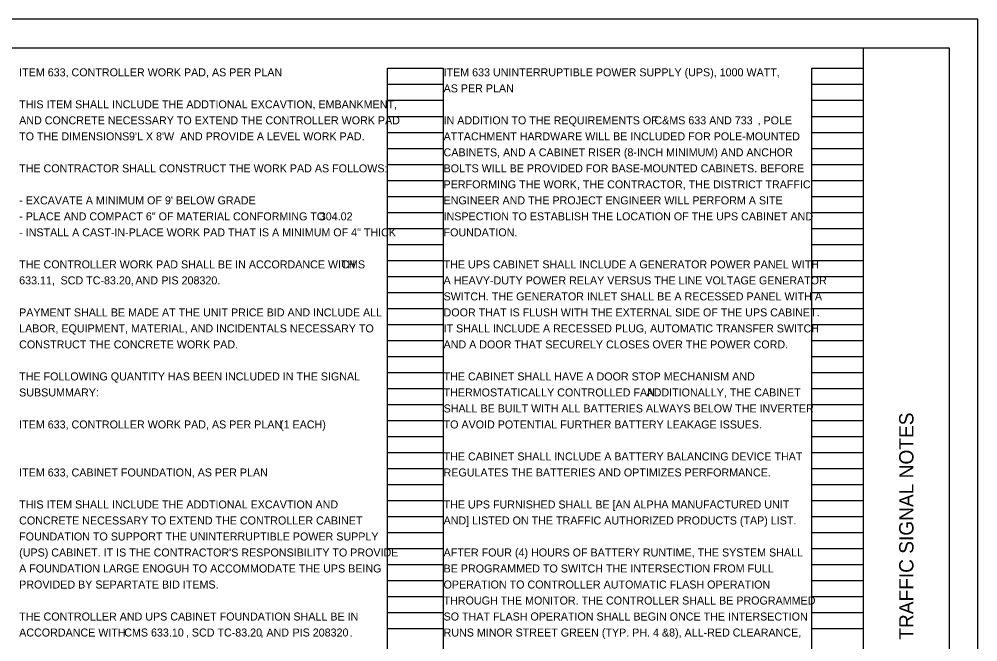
# Model space of a CAD drawing. Extents: x 0 to 34, y 0 to 22.
# Drawn here: x 17.24 to 34, y 11.11 to 22 of the extents above; entities that cross this region are included whole.
import ezdxf

# ---------------------------------------------------------------- set-up
doc = ezdxf.new("R2010")
doc.units = 0
for name, color, linetype in [('SH_Border', 7, 'Continuous'), ('SH_Cut_Line', 7, 'Continuous'), ('SH_Data', 7, 'Continuous'), ('SH_Text', 7, 'Continuous')]:
    doc.layers.add(name, color=color, linetype=linetype)

msp = doc.modelspace()

# ---------------------------------------------------------------- linework, layer by layer
at = {"layer": 'SH_Border'}
msp.add_line((32, 0.5), (32, 21.5), dxfattribs=at)
msp.add_lwpolyline([(1.5, 21.5), (33.5, 21.5), (33.5, 0.5), (1.5, 0.5)], close=True, dxfattribs=at)
at = {"layer": 'SH_Cut_Line'}
msp.add_lwpolyline([(0, 0), (34, 0), (34, 22), (0, 22)], close=True, dxfattribs=at)
at = {"layer": 'SH_Data'}
for p, q in [((23.68, 0.98), (23.68, 21.14)), ((23.68, 21.14), (24.66, 21.14)), ((24.66, 0.98), (24.66, 21.14)), ((31.1, 0.98), (31.1, 21.14)), ((31.1, 21.14), (32, 21.14)), ((32, 0.98), (32, 21.14)), ((23.68, 20.86), (24.66, 20.86)), ((31.1, 20.86), (32, 20.86)), ((23.68, 20.58), (24.66, 20.58)), ((31.1, 20.58), (32, 20.58)), ((23.68, 20.3), (24.66, 20.3)), ((31.1, 20.3), (32, 20.3)), ((23.68, 20.02), (24.66, 20.02)), ((31.1, 20.02), (32, 20.02)), ((23.68, 19.74), (24.66, 19.74)), ((31.1, 19.74), (32, 19.74)), ((23.68, 19.46), (24.66, 19.46)), ((31.1, 19.46), (32, 19.46)), ((23.68, 19.18), (24.66, 19.18)), ((31.1, 19.18), (32, 19.18)), ((23.68, 18.9), (24.66, 18.9)), ((31.1, 18.9), (32, 18.9)), ((23.68, 18.62), (24.66, 18.62)), ((31.1, 18.62), (32, 18.62)), ((23.68, 18.34), (24.66, 18.34)), ((31.1, 18.34), (32, 18.34)), ((23.68, 18.06), (24.66, 18.06)), ((31.1, 18.06), (32, 18.06)), ((23.68, 17.78), (24.66, 17.78)), ((31.1, 17.78), (32, 17.78)), ((23.68, 17.5), (24.66, 17.5)), ((31.1, 17.5), (32, 17.5)), ((23.68, 17.22), (24.66, 17.22)), ((31.1, 17.22), (32, 17.22)), ((23.68, 16.94), (24.66, 16.94)), ((31.1, 16.94), (32, 16.94)), ((23.68, 16.66), (24.66, 16.66)), ((31.1, 16.66), (32, 16.66)), ((23.68, 16.38), (24.66, 16.38)), ((31.1, 16.38), (32, 16.38)), ((23.68, 16.1), (24.66, 16.1)), ((31.1, 16.1), (32, 16.1)), ((23.68, 15.82), (24.66, 15.82)), ((31.1, 15.82), (32, 15.82)), ((23.68, 15.54), (24.66, 15.54)), ((31.1, 15.54), (32, 15.54)), ((23.68, 15.26), (24.66, 15.26)), ((31.1, 15.26), (32, 15.26)), ((23.68, 14.98), (24.66, 14.98)), ((31.1, 14.98), (32, 14.98)), ((23.68, 14.7), (24.66, 14.7)), ((31.1, 14.7), (32, 14.7)), ((23.68, 14.42), (24.66, 14.42)), ((31.1, 14.42), (32, 14.42)), ((23.68, 14.14), (24.66, 14.14)), ((31.1, 14.14), (32, 14.14)), ((23.68, 13.86), (24.66, 13.86)), ((31.1, 13.86), (32, 13.86)), ((23.68, 13.58), (24.66, 13.58)), ((31.1, 13.58), (32, 13.58)), ((23.68, 13.3), (24.66, 13.3)), ((31.1, 13.3), (32, 13.3)), ((23.68, 13.02), (24.66, 13.02)), ((31.1, 13.02), (32, 13.02)), ((23.68, 12.74), (24.66, 12.74)), ((31.1, 12.74), (32, 12.74)), ((23.68, 12.46), (24.66, 12.46)), ((31.1, 12.46), (32, 12.46)), ((23.68, 12.18), (24.66, 12.18)), ((31.1, 12.18), (32, 12.18)), ((23.68, 11.9), (24.66, 11.9)), ((31.1, 11.9), (32, 11.9)), ((23.68, 11.62), (24.66, 11.62)), ((31.1, 11.62), (32, 11.62)), ((23.68, 11.34), (24.66, 11.34)), ((31.1, 11.34), (32, 11.34))]:
    msp.add_line(p, q, dxfattribs=at)

# ---------------------------------------------------------------- texts
msp.add_text('TRAFFIC SIGNAL NOTES', height=0.25, rotation=90, dxfattribs=at).set_placement((32.875, 11.144))
at = {"layer": 'SH_Text'}
for s, p in [('ITEM 633, CONTROLLER WORK PAD, AS PER PLAN', (17.24, 21)), ('ITEM 633 UNINTERRUPTIBLE POWER SUPPLY (UPS), 1000 WATT,', (24.66, 21)), ('AS PER PLAN', (24.66, 20.72)), ('THIS ITEM SHALL INCLUDE THE ADDTIONAL EXCAVTION, EMBANKMENT,', (17.24, 20.44)), ('AND CONCRETE NECESSARY TO EXTEND THE CONTROLLER WORK PAD', (17.24, 20.16)), ('IN ADDITION TO THE REQUIREMENTS OF ', (24.66, 20.16)), ('C&MS 633 AND 733', (28.346, 20.16)), (', POLE', (30.149, 20.16)), ('TO THE DIMENSIONS ', (17.24, 19.88)), ("9'L X 8'W", (19.16, 19.88)), (' AND PROVIDE A LEVEL WORK PAD.', (20.001, 19.88)), ('ATTACHMENT HARDWARE WILL BE INCLUDED FOR POLE-MOUNTED', (24.66, 19.88)), ('CABINETS, AND A CABINET RISER (8-INCH MINIMUM) AND ANCHOR', (24.66, 19.6)), ('THE CONTRACTOR SHALL CONSTRUCT THE WORK PAD AS FOLLOWS:', (17.24, 19.32)), ('BOLTS WILL BE PROVIDED FOR BASE-MOUNTED CABINETS. BEFORE', (24.66, 19.32)), ('PERFORMING THE WORK, THE CONTRACTOR, THE DISTRICT TRAFFIC', (24.66, 19.04)), ("- EXCAVATE A MINIMUM OF 9' BELOW GRADE", (17.24, 18.76)), ('ENGINEER AND THE PROJECT ENGINEER WILL PERFORM A SITE', (24.66, 18.76)), ('- PLACE AND COMPACT 6" OF MATERIAL CONFORMING TO ', (17.24, 18.48)), ('304.02', (22.496, 18.48)), ('INSPECTION TO ESTABLISH THE LOCATION OF THE UPS CABINET AND', (24.66, 18.48)), ('- INSTALL A CAST-IN-PLACE WORK PAD THAT IS A MINIMUM OF 4" THICK', (17.24, 18.2)), ('FOUNDATION.', (24.66, 18.2)), ('THE CONTROLLER WORK PAD SHALL BE IN ACCORDANCE WITH ', (17.24, 17.64)), ('CMS', (22.872, 17.64)), ('THE UPS CABINET SHALL INCLUDE A GENERATOR POWER PANEL WITH', (24.66, 17.64)), ('633.11,', (17.24, 17.36)), ('SCD TC-83.20,', (17.964, 17.36)), (' AND ', (19.221, 17.36)), ('PIS 208320.', (19.726, 17.36)), ('A HEAVY-DUTY POWER RELAY VERSUS THE LINE VOLTAGE GENERATOR', (24.66, 17.36)), ('SWITCH. THE GENERATOR INLET SHALL BE A RECESSED PANEL WITH A', (24.66, 17.08)), ('PAYMENT SHALL BE MADE AT THE UNIT PRICE BID AND INCLUDE ALL', (17.24, 16.8)), ('DOOR THAT IS FLUSH WITH THE EXTERNAL SIDE OF THE UPS CABINET.', (24.66, 16.8)), ('LABOR, EQUIPMENT, MATERIAL, AND INCIDENTALS NECESSARY TO', (17.24, 16.52)), ('IT SHALL INCLUDE A RECESSED PLUG, AUTOMATIC TRANSFER SWITCH', (24.66, 16.52)), ('CONSTRUCT THE CONCRETE WORK PAD.', (17.24, 16.24)), ('AND A DOOR THAT SECURELY CLOSES OVER THE POWER CORD.', (24.66, 16.24)), ('THE FOLLOWING QUANTITY HAS BEEN INCLUDED IN THE SIGNAL', (17.24, 15.68)), ('THE CABINET SHALL HAVE A DOOR STOP MECHANISM AND', (24.66, 15.68)), ('SUBSUMMARY:', (17.24, 15.4)), ('THERMOSTATICALLY CONTROLLED FAN. ', (24.66, 15.4)), ('ADDITIONALLY, THE CABINET', (28.208, 15.4)), ('SHALL BE BUILT WITH ALL BATTERIES ALWAYS BELOW THE INVERTER', (24.66, 15.12)), ('ITEM 633, CONTROLLER WORK PAD, AS PER PLAN', (17.24, 14.84)), ('(1 EACH)', (21.801, 14.84)), ('TO AVOID POTENTIAL FURTHER BATTERY LEAKAGE ISSUES.', (24.66, 14.84)), ('THE CABINET SHALL INCLUDE A BATTERY BALANCING DEVICE THAT', (24.66, 14.28)), ('ITEM 633, CABINET FOUNDATION, AS PER PLAN', (17.24, 14)), ('REGULATES THE BATTERIES AND OPTIMIZES PERFORMANCE. ', (24.66, 14)), ('THIS ITEM SHALL INCLUDE THE ADDTIONAL EXCAVTION AND', (17.24, 13.44)), ('THE UPS FURNISHED SHALL BE [AN ALPHA MANUFACTURED UNIT', (24.66, 13.44)), ('CONCRETE NECESSARY TO EXTEND THE CONTROLLER CABINET', (17.24, 13.16)), ('AND] LISTED ON THE TRAFFIC AUTHORIZED PRODUCTS (TAP) LIST.', (24.66, 13.16)), ('FOUNDATION TO SUPPORT THE UNINTERRUPTIBLE POWER SUPPLY', (17.24, 12.88)), ("(UPS) CABINET. IT IS THE CONTRACTOR'S RESPONSIBILITY TO PROVIDE", (17.24, 12.6)), ('AFTER FOUR (4) HOURS OF BATTERY RUNTIME, THE SYSTEM SHALL', (24.66, 12.6)), ('A FOUNDATION LARGE ENOGUH TO ACCOMMODATE THE UPS BEING', (17.24, 12.32)), ('BE PROGRAMMED TO SWITCH THE INTERSECTION FROM FULL', (24.66, 12.32)), ('PROVIDED BY SEPARTATE BID ITEMS.', (17.24, 12.04)), ('OPERATION TO CONTROLLER AUTOMATIC FLASH OPERATION', (24.66, 12.04)), ('THROUGH THE MONITOR. THE CONTROLLER SHALL BE PROGRAMMED', (24.66, 11.76)), ('THE CONTROLLER AND UPS CABINET FOUNDATION SHALL BE IN', (17.24, 11.48)), ('SO THAT FLASH OPERATION SHALL BEGIN ONCE THE INTERSECTION', (24.66, 11.48)), ('ACCORDANCE WITH ', (17.24, 11.2)), ('CMS 633.10', (19.077, 11.2)), ('SCD TC-83.20', (20.259, 11.2)), (', AND ', (21.459, 11.2)), ('PIS 208320', (22.019, 11.2)), ('RUNS MINOR STREET GREEN (TYP. PH. 4 &8), ALL-RED CLEARANCE,', (24.66, 11.2)), (', ', (20.154, 11.2)), ('.', (23.018, 11.2))]:
    msp.add_text(s, height=0.14, dxfattribs=at).set_placement(p)

doc.saveas('drawing.dxf')
